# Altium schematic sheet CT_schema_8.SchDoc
size 277 x 170 mm
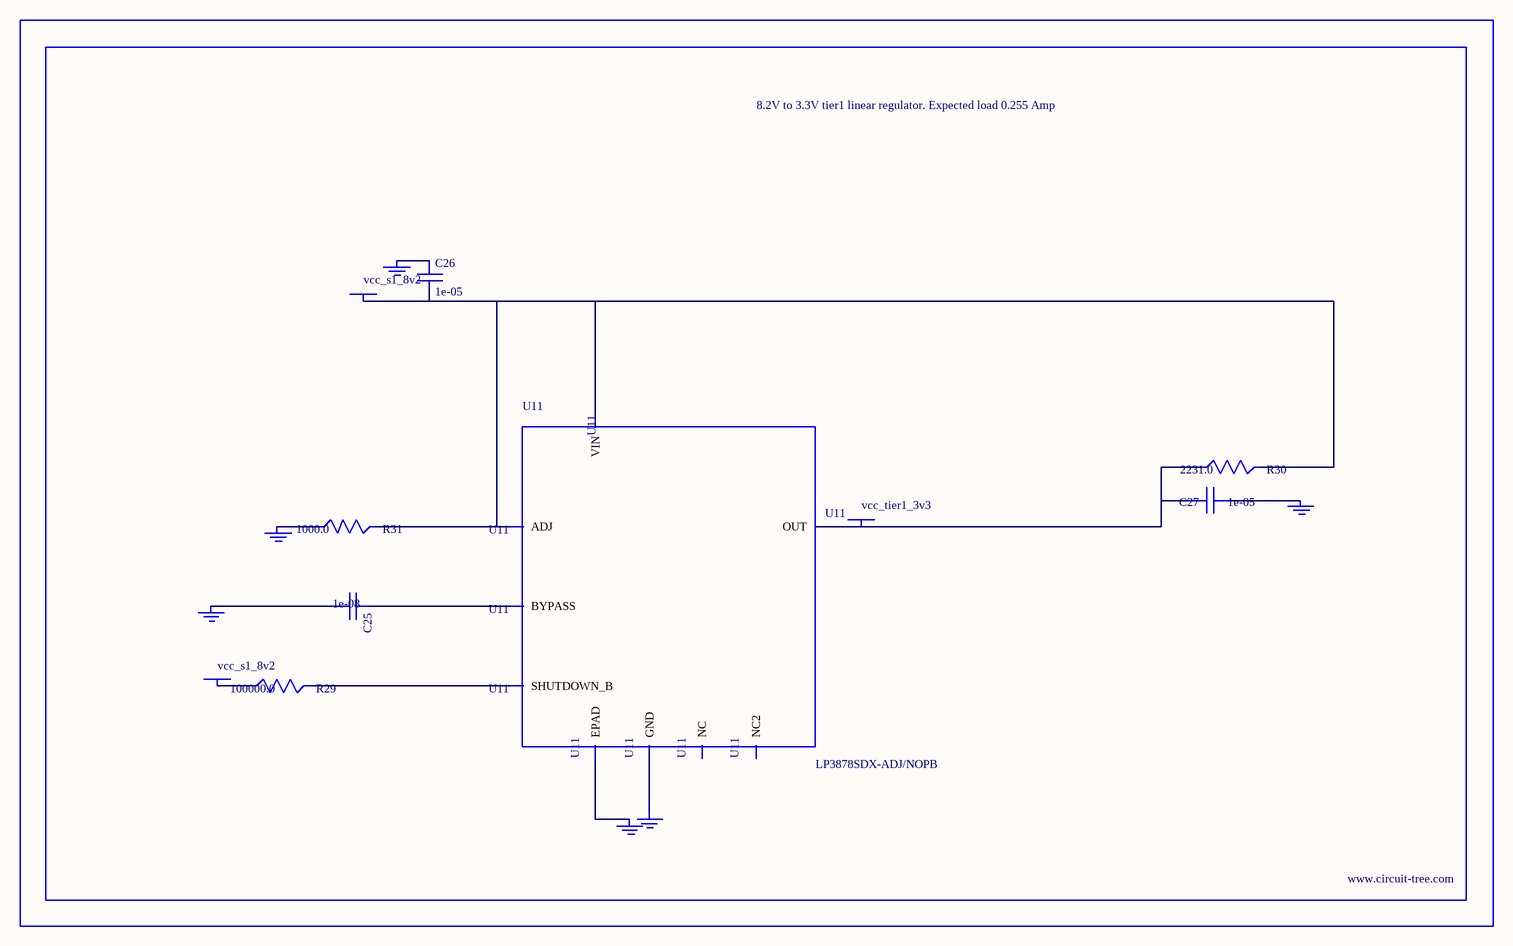
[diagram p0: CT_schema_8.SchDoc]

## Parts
BORDER7  (no value)
C25  1e-08  [C0402]
C26  1e-05  [C1206]
C27  1e-05  [C1210]
GND_INSTANCE_7_0  (no value)
GND_INSTANCE_7_1  (no value)
GND_INSTANCE_7_2  (no value)
GND_INSTANCE_7_3  (no value)
GND_INSTANCE_7_4  (no value)
GND_INSTANCE_7_5  (no value)
POWER_INSTANCE_7_0  vcc_s1_8v2
POWER_INSTANCE_7_1  vcc_s1_8v2
POWER_INSTANCE_7_2  vcc_tier1_3v3
R29  100000.0  [R0603]
R30  2231.0  [R0603]
R31  1000.0  [R0603]
U11  LP3878SDX-ADJ/NOPB  [WSON-8]

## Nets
NetC25_1: C25.1 U11.1(BYPASS)
NetC25_2: C25.2 GND_INSTANCE_7_0.0(GND)
NetC26_1: C26.1 GND_INSTANCE_7_1.0(GND)
NetC26_2: C26.2 POWER_INSTANCE_7_0.0(PWR) R30.2 R31.2 U11.4(VIN) U11.6(ADJ)
NetC27_1: C27.1 GND_INSTANCE_7_2.0(GND)
NetC27_2: C27.2 POWER_INSTANCE_7_2.0(PWR) R30.1 U11.5(OUT)
NetGND_INSTANCE_7_3_0: GND_INSTANCE_7_3.0(GND) R31.1
NetGND_INSTANCE_7_4_0: GND_INSTANCE_7_4.0(GND) U11.PAD(EPAD)
NetGND_INSTANCE_7_5_0: GND_INSTANCE_7_5.0(GND) U11.3(GND)
NetPOWER_INSTANCE_7_1_0: POWER_INSTANCE_7_1.0(PWR) R29.1
NetR29_2: R29.2 U11.8(SHUTDOWN_B)

Not connected (* = marked no-connect by the designer): U11 2(NC) 7(NC2)

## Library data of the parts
BORDER7 = BORDER_PAGE7
C25 = C0402C103K3RAC
C26 = C1206C106K3RACTU
C27 = GRM32DR61E106MA12L
GND_INSTANCE_7_0-GND_INSTANCE_7_5 = GND
POWER_INSTANCE_7_0-POWER_INSTANCE_7_2 = PWR
R29 = RC0603JR-07100KL
R30 = R30
R31 = RC0603JR-071KL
